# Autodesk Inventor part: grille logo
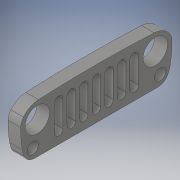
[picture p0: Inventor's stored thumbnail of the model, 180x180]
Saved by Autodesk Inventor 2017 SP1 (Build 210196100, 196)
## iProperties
Created: 2017-08
Part Number: grille logo
Material: Generic
Document SubType Name: Modeling
Designer: wh1ter0se
Density: 1 g/cm^3
Appearance: Smooth - Medium Gray
Author: wh1ter0se
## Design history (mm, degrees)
sketch "Sketch1" dims "d18" = 25.4
  geometry: L1 (-9.077, -8.4)-(-9.077, -67.793); L2 (-25.355, -7.136)-(-25.355, -38.097); L3 (-19.409, -35.961)-(-6.322, -35.961); L4 (-4.186, -38.097)-(-21.545, -38.097); L5 (-6.322, -40.233)-(-19.409, -40.233); L6 (-19.409, -29.636)-(-6.322, -29.636); L7 (-6.322, -33.908)-(-19.409, -33.908); L8 (-19.409, -23.311)-(-6.322, -23.311); L9 (-6.322, -27.583)-(-19.409, -27.583); L10 (-19.409, -16.987)-(-6.322, -16.987); L11 (-6.322, -21.259)-(-19.409, -21.259); L12 (-6.322, -42.285)-(-19.409, -42.285); L13 (-19.409, -40.233)-(-6.322, -40.233); L14 (-6.322, -35.961)-(-19.409, -35.961); L15 (-19.409, -46.557)-(-6.322, -46.557); L16 (-19.409, -52.882)-(-6.322, -52.882); L17 (-6.322, -48.61)-(-19.409, -48.61); L18 (-19.409, -59.206)-(-6.322, -59.206); L19 (-6.322, -54.934)-(-19.409, -54.934); L20 (-9.077, -67.793)-(-9.077, -8.4); L21 (-25.355, -69.057)-(-25.355, -38.097); C1 r 6.151 at (-9.077, -8.4); C2 r 2.862 at (-20.342, -6.041); C3 r 6.151 at (-9.077, -67.793); C4 r 2.862 at (-20.342, -70.152); A1 r 591.924 centre (-591.924, -38.097) between (0, -38.097) and (-0.717, -8.972); A2 r 10.418 centre (-11.122, -9.485) between (-0.717, -8.972) and (-4.536, -1.413); A3 r 6.256 centre (-8.491, -6.26) between (-4.536, -1.413) and (-8.391, -0.005); A4 r 51.942 centre (-9.219, -51.941) between (-8.391, -0.005) and (-18.548, -0.843); A5 r 16.831 centre (-15.525, -17.4) between (-18.548, -0.843) and (-21.668, -1.731); A6 r 5.805 centre (-19.549, -7.136) between (-21.668, -1.731) and (-25.355, -7.136); A7 r 2.136 centre (-19.409, -38.097) between (-19.409, -35.961) and (-19.409, -40.233); A8 r 2.136 centre (-6.322, -38.097) between (-6.322, -40.233) and (-6.322, -35.961); A9 r 2.136 centre (-6.322, -31.772) between (-6.322, -33.908) and (-6.322, -29.636); A10 r 2.136 centre (-19.409, -31.772) between (-19.409, -29.636) and (-19.409, -33.908); A11 r 2.136 centre (-6.322, -25.447) between (-6.322, -27.583) and (-6.322, -23.311); A12 r 2.136 centre (-19.409, -25.447) between (-19.409, -23.311) and (-19.409, -27.583); A13 r 2.136 centre (-6.322, -19.123) between (-6.322, -21.259) and (-6.322, -16.987); A14 r 2.136 centre (-19.409, -19.123) between (-19.409, -16.987) and (-19.409, -21.259); A15 r 5.805 centre (-19.549, -69.057) between (-25.355, -69.057) and (-21.668, -74.463); A16 r 16.831 centre (-15.525, -58.793) between (-21.668, -74.463) and (-18.548, -75.35); A17 r 51.942 centre (-9.219, -24.253) between (-18.548, -75.35) and (-8.391, -76.188); A18 r 6.256 centre (-8.491, -69.933) between (-8.391, -76.188) and (-4.536, -74.78); A19 r 10.418 centre (-11.122, -66.708) between (-4.536, -74.78) and (-0.717, -67.221); A20 r 2.136 centre (-6.322, -38.097) between (-6.322, -40.233) and (-6.322, -35.961); A21 r 2.136 centre (-19.409, -38.097) between (-19.409, -35.961) and (-19.409, -40.233); A22 r 2.136 centre (-6.322, -44.421) between (-6.322, -46.557) and (-6.322, -42.285); A23 r 2.136 centre (-19.409, -44.421) between (-19.409, -42.285) and (-19.409, -46.557); A24 r 2.136 centre (-6.322, -50.746) between (-6.322, -52.882) and (-6.322, -48.61); A25 r 2.136 centre (-19.409, -50.746) between (-19.409, -48.61) and (-19.409, -52.882); A26 r 2.136 centre (-19.409, -57.07) between (-19.409, -54.934) and (-19.409, -59.206); A27 r 591.924 centre (-591.924, -38.097) between (-0.717, -67.221) and (0, -38.097); A28 r 2.136 centre (-6.322, -57.07) between (-6.322, -59.206) and (-6.322, -54.934); 9 further points
  constraints: 63 point on circle, 42 end point, 39 symmetric about line, 32 centre point, 5 tangent, 2 horizontal, 2 point on line, 2 vertical, 1 coincident, 49 other
  dimensions: "d15" = 6.3246 distance of A8.centre A9.centre
extrude "Extrusion1" new body sketch "Sketch1" distance "d24" = 6.35; taper "d25" = 0 deg
body "Solid1"
